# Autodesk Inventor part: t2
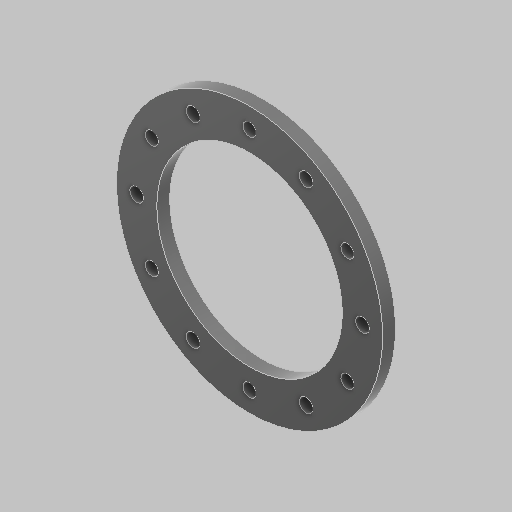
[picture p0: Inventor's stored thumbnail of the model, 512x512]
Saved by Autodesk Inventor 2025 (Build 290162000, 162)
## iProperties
Created: 2025-01
Part Number: t2
Material: Thermoplastic Resin
Document SubType Name: Modeling
Designer: dansp
Density: 1.28 g/cm^3
Appearance: Smooth - Black
Mass: 13.2627 g
Surface Area: 75.5829 cm^2
Volume: 10.3615 cm^3
Author: dansp
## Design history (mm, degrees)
sketch "Sketch1"
  geometry: L1 (0, 57.75)-(0, -57.75) reference; L2 (-57.75, 0)-(57.75, 0) reference; C1 r 41.25 at (0, 0); C2 r 28.75 at (0, 0); 1 further point
  constraints: 2 centre point, 2 coincident
  dimensions: "d0" = 82.5 diameter of C1; "d1" = 12.5 radial gap between concentric circles of C1 C2
extrude "Extrusion1" new body sketch "Sketch1" distance "d2" = 4; taper "d3" = 0 deg
sketch "Sketch2"
  geometry: L1 (0, 57.75)-(0, -57.75) reference; 8 further points
  constraints: 3 point on line, 2 coincident, 2 vertical alignment, 2 other
  dimensions: "d157" = 12.5 distance of point (0, 41.25) point (0, 28.75) (derived); "d158" = 6.25 distance of point (0, 35) point (0, 28.75) (= 0.5 x d157)
hole "Hole1" sketch "Sketch2" at (0, 35) diameter "d5" = 4; stored, may be unused: countersink angle "d9" = 90 deg, drill point angle "d11" = 118 deg; dims "d6" = 12, "d7" = 4, "d8" = 2, "d10" = 8
pattern_circular "Circular Pattern2" dims angle "d18" = 360 deg
sketch "Sketch17"
  geometry: L1 (0, 0)-(-17.5, 30.311); L2 (0, -57.75)-(0, 57.75) reference; L3 (0, 0)-(20.74, -35.923); C1 r 2 at (-30.311, 17.5) reference; C2 r 2.1 at (-17.5, 30.311); C3 r 2.1 at (17.5, -30.311); A1 r 35 centre (0, 0) between (-30.311, 17.5) and (-17.5, 30.311); 1 further point
  constraints: 4 end point, 3 centre point, 3 point on circle, 1 coincident, 1 collinear, 1 point on line
  dimensions: "d148" = 4.2 diameter of C2; "d150" = 30 deg angle of L2 L1; "d151" = 4.2 diameter of C3 (= d148)
extrude "Extrusion3" cut sketch "Sketch17" extent not by distance; stored distance "d152" = 0; taper "d153" = 0 deg
pattern_circular "Circular Pattern3" dims angle "d155" = 360 deg
body "Solid1"
node "Projected Loop1"
other parameters: "d39" = 55 deg [user parameter], "Sketch3_Pitch" = 0.7 [user parameter], "d57" = 55 deg [user parameter], "Sketch5_Pitch" = 0.7 [user parameter], "d75" = 55 deg [user parameter], "Sketch7_Pitch" = 0.7 [user parameter], "d93" = 55 deg [user parameter], "Sketch9_Pitch" = 0.7 [user parameter], "d111" = 55 deg [user parameter], "Sketch11_Pitch" = 0.7 [user parameter], "d129" = 55 deg [user parameter], "Sketch13_Pitch" = 0.7 [user parameter]
